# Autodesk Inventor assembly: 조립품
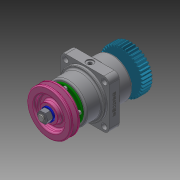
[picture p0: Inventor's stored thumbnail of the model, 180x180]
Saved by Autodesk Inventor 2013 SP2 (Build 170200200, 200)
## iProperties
Created: 2023-10
Part Number: 조립품
Document SubType Name: Assembly
Designer: i
Author: i
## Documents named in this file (12)
- C:\Users\i\Desktop\731006V1006\조립품.iam
- C:\Users\i\Desktop\731006V1006\본체.ipt
- C:\Users\i\Desktop\731006V1006\V벨트풀리.ipt
- C:\Users\i\Desktop\731006V1006\너트 M12x1.25.ipt
- C:\Users\i\Desktop\731006V1006\베어링 6204.ipt
- C:\Users\i\Desktop\731006V1006\볼트 M4x0.7.ipt
- C:\Users\i\Desktop\731006V1006\스퍼기어.ipt
- C:\Users\i\Desktop\731006V1006\오일실 20x35x8.ipt
- C:\Users\i\Desktop\731006V1006\와셔 12x24.ipt
- C:\Users\i\Desktop\731006V1006\축.ipt
- C:\Users\i\Desktop\731006V1006\커버.ipt
- C:\Users\i\Desktop\731006V1006\키 5x5.ipt
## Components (1 placed, 1 different names)
1. V벨트풀리:1
